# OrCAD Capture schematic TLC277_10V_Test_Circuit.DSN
size A; title: TLC272, TLC272A, TLC272B, TLC272Y, TLC277 LinCMOS; rev: 1.1; note: Datasheet: SLOS091E EVM: N/A
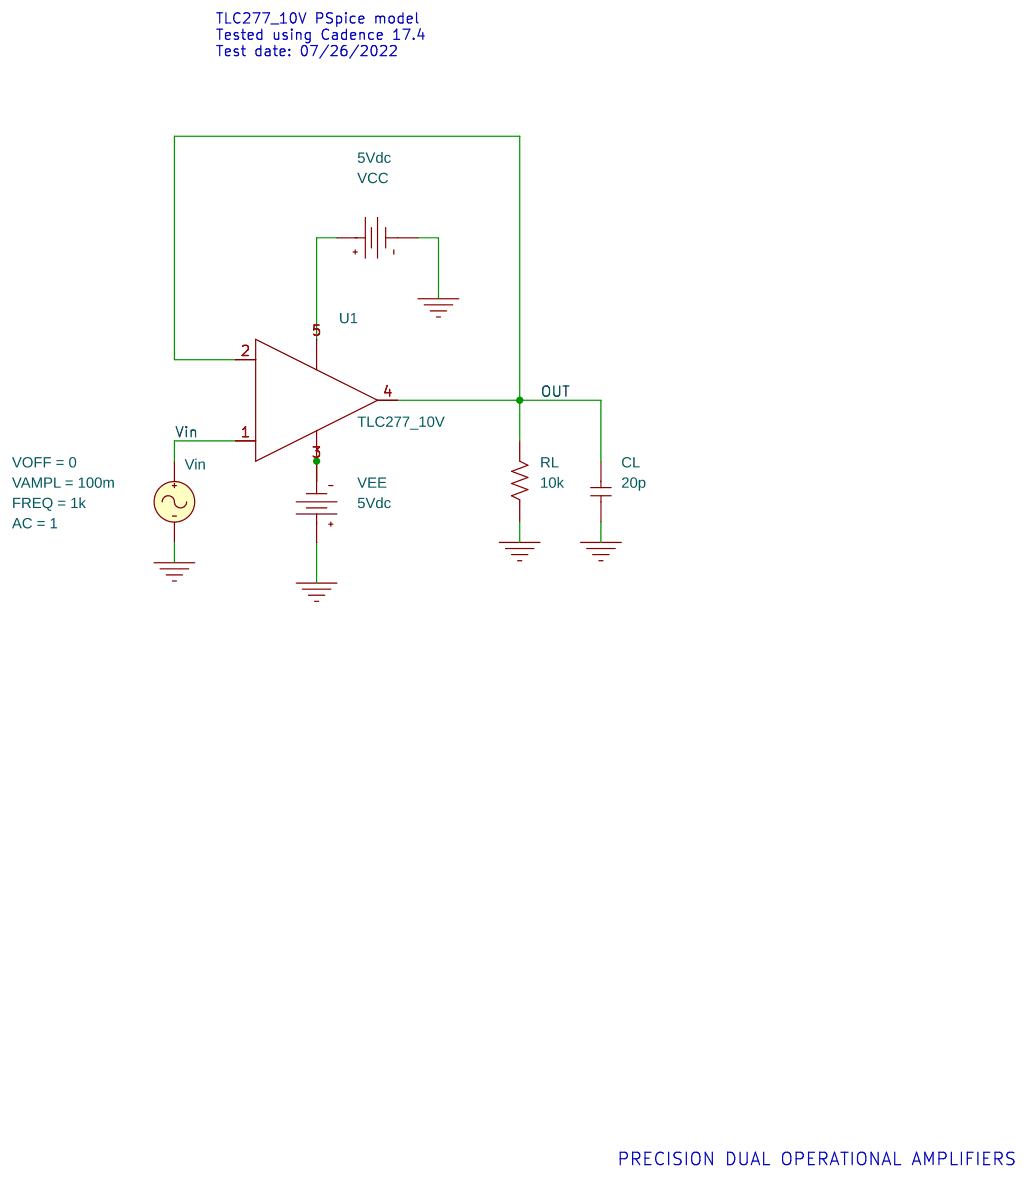
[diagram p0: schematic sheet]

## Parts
CL  20p  [RAD/CK05]
RL  10k  [AX/RC05]
U1  TLC277_10V
VCC  VDC
VEE  VDC
Vin  VSIN

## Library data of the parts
CL = C
RL = R
U1 = TLC277_10V
VCC VEE = VDC: DC: 5Vdc
Vin = VSIN: AC: 1; FREQ: 1k; VAMPL: 100m; VOFF: 0

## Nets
Vin: U1.1(+) Vin.1(+)
0: CL.1 RL.1 VCC.1(-) VEE.0(+) Vin.2(-)
OUT: CL.2 RL.2 U1.2(-) U1.4(OUT)
N22995: U1.5(V+) VCC.0(+)
N23017: U1.3(V-) VEE.1(-)

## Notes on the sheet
- TLC277_10V PSpice model
  Tested using Cadence 17.4
  Test date: 07/26/2022
- PRECISION DUAL OPERATIONAL AMPLIFIERS
